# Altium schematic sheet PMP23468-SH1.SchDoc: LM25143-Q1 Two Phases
size 431 x 279 mm; Date: Not shown in title block; ApprovedBy: Not shown in title block; CheckedBy: Not shown in title block; Author: Not shown in title block; CompanyName: Not shown in title block; Engineer: Not shown in title block; Organization: Not shown in title block; Address1: Not shown in title block; Address2: Not shown in title block; Address3: Not shown in title block; Address4: Not shown in title block; DocumentNumber: 1; Revision: Use project parameter SCH_Rev; SheetNumber: 1; SheetTotal: 2; PageSetup: Record=PageOptions¦CenterHorizontal=True¦CenterVertical=True¦PrintScale=0.96¦XCorrection=1.00¦YCorrection=1.00¦PrintKind=0¦BorderSize=5000000¦LeftOffset=0¦BottomOffset=0¦Orientation=2¦PaperLength=1000¦PaperWidth=1000¦Scale=100¦PaperSource=7¦PrintQuality=600¦MediaType=1¦DitherType=10¦PaperKind=11" x 17"¦PrintScaleMode=1
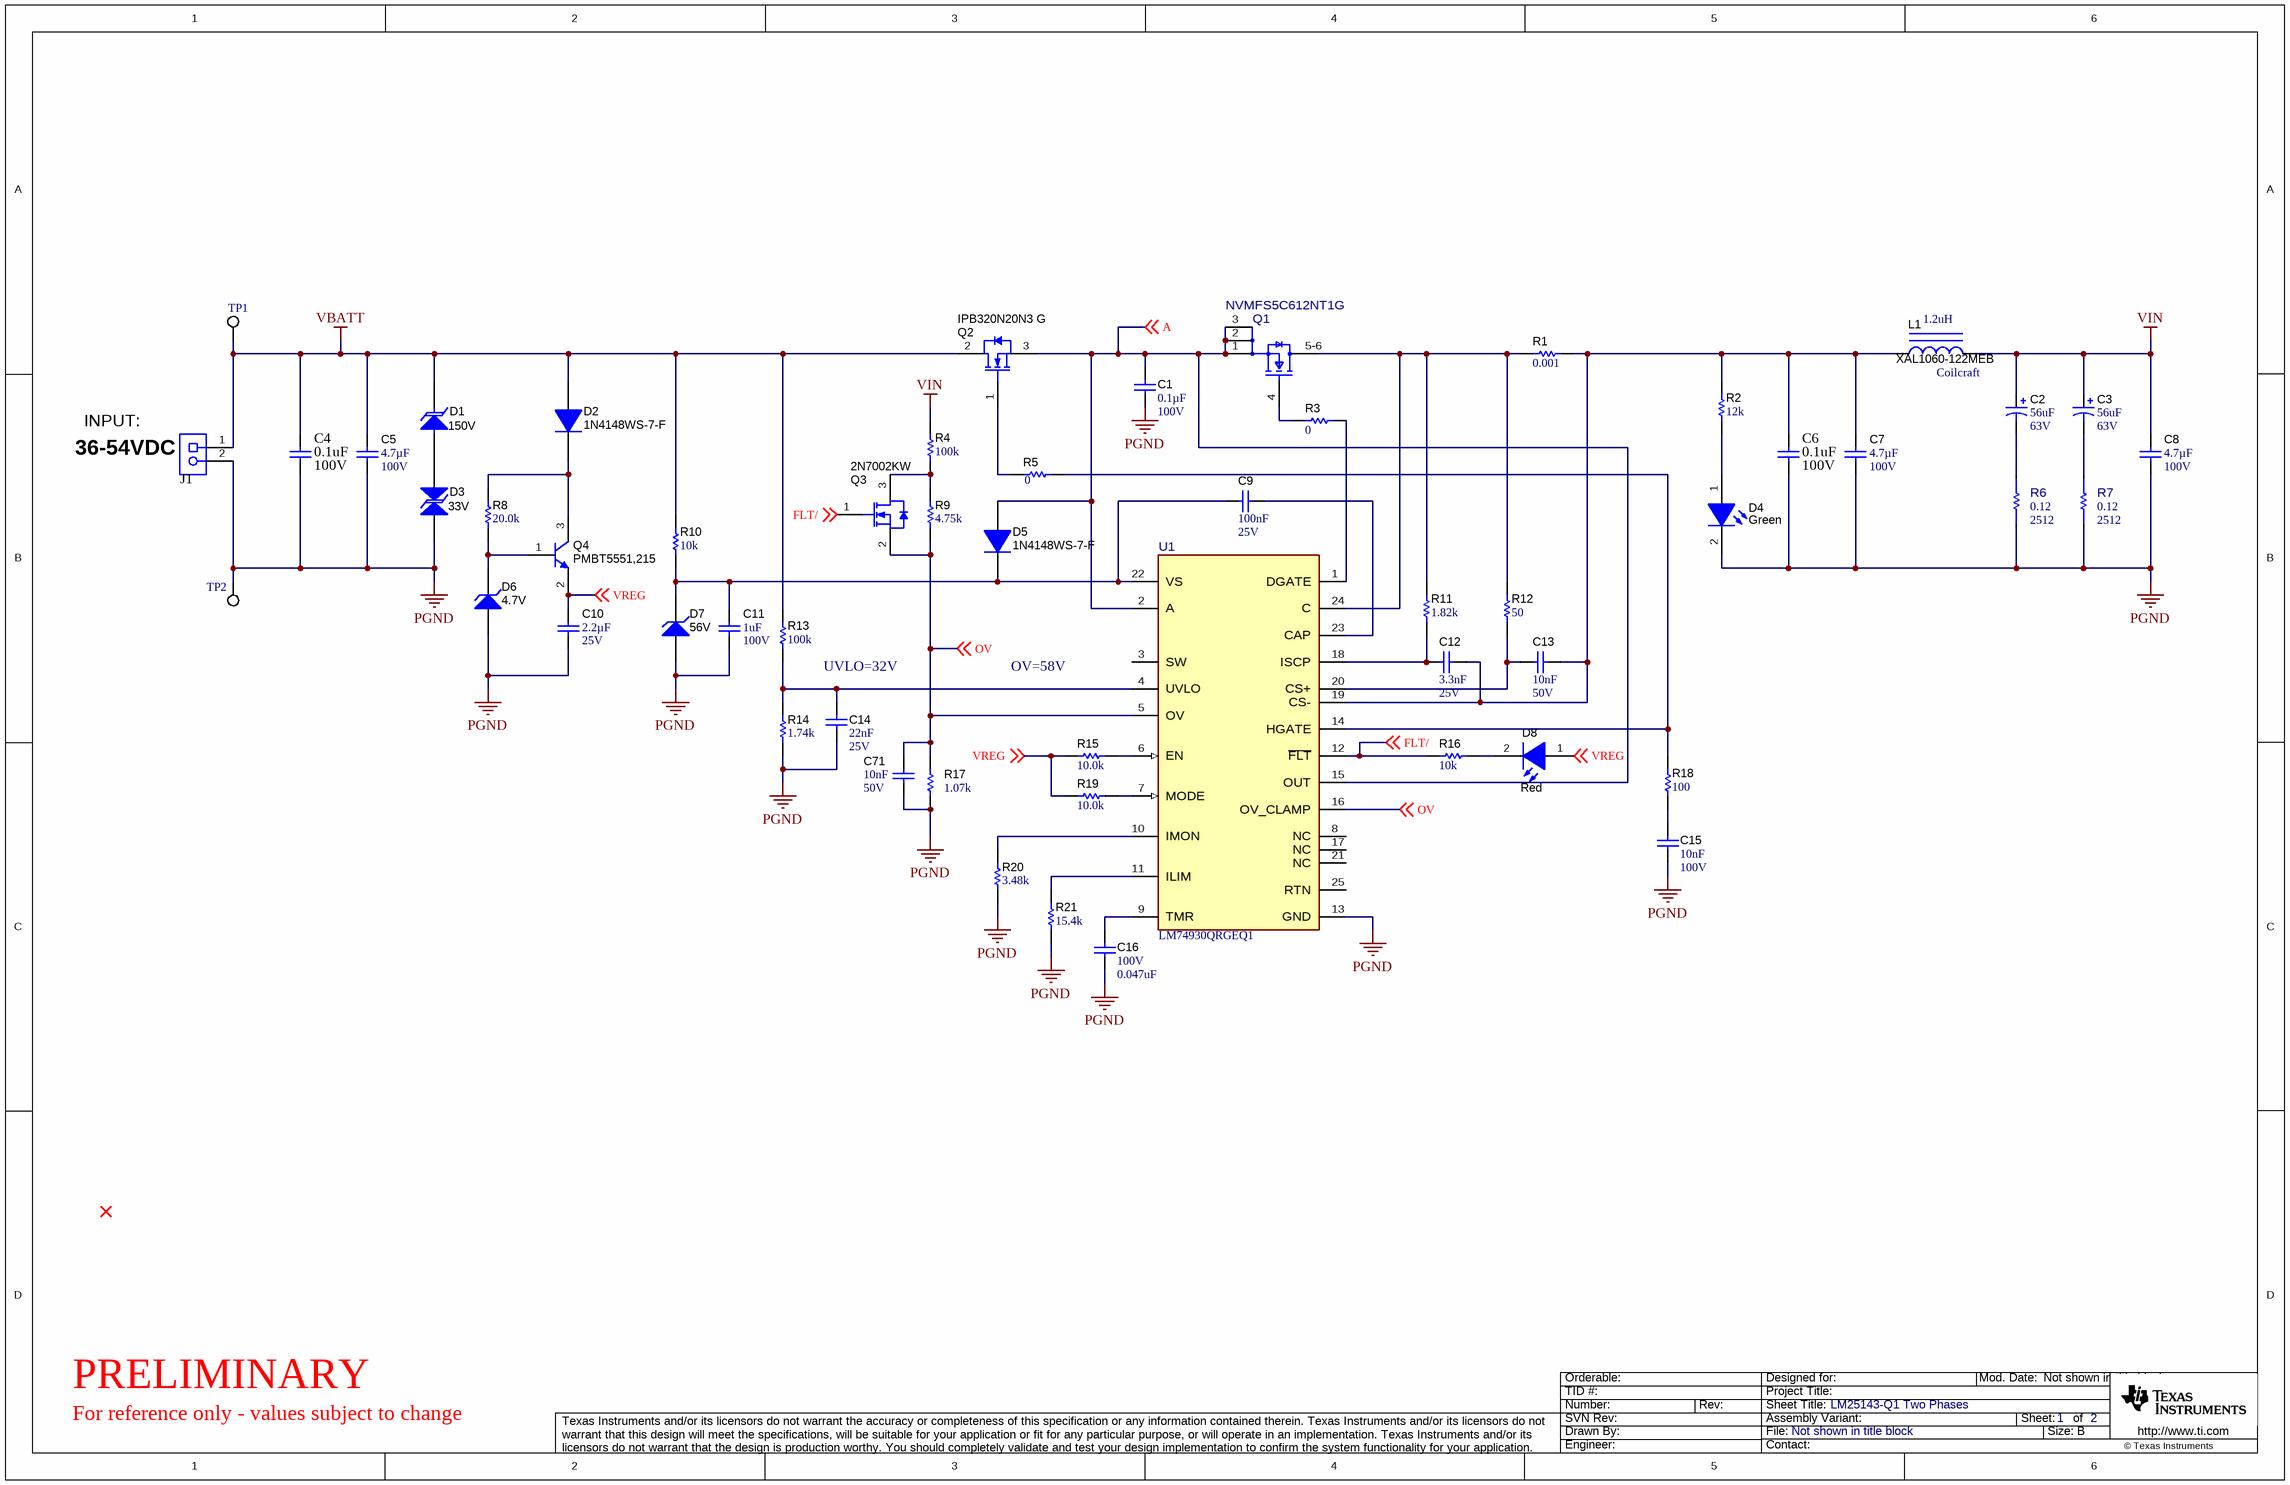
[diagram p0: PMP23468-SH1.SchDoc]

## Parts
C1  ValueDisplayed: 0.1µF  VDC_V: 100V  [0603]  (hidden comment: GCJ188L8EL104KA07D)
C2  VDC_V: 63V  ValueDisplayed: 56uF  [SM_RADIAL_10BMM]  (hidden comment: EEHZC1J560P)
C3  VDC_V: 63V  ValueDisplayed: 56uF  [SM_RADIAL_10BMM]  (hidden comment: EEHZC1J560P)
C4  Value2: 100V  ValueDisplayed: 0.1uF  [0805_HV]  (hidden comment: C0805C104K1RACTU)
C5  VDC_V: 100V  ValueDisplayed: 4.7µF  [1210_220]  (hidden comment: GCM32DC72A475KE02L)
C6  Value2: 100V  ValueDisplayed: 0.1uF  [0805_HV]  (hidden comment: C0805C104K1RACTU)
C7  VDC_V: 100V  ValueDisplayed: 4.7µF  [1210_220]  (hidden comment: GCM32DC72A475KE02L)
C8  VDC_V: 100V  ValueDisplayed: 4.7µF  [1210_220]  (hidden comment: GCM32DC72A475KE02L)
C9  Cap_F: 100nF  VDC_V: 25V  [0603]  (hidden comment: CGA3E2X7R1E104K080AA)
C10  Cap_F: 2.2µF  VDC_V: 25V  [0805_HV]  (hidden comment: GCM21BR71E225KA73L)
C11  VDC_V: 100V  ValueDisplayed: 1uF  [1206_180]  (hidden comment: GCM31CR72A105KA03)
C12  Cap_F: 3.3nF  VDC_V: 25V  [0603]  (hidden comment: GRM188R71E332KA01D)
C13  Cap_F: 10nF  VDC_V: 50V  [0603]  (hidden comment: GCM188R71H103KA37D)
C14  Cap_F: 22nF  VDC_V: 25V  [0603]  (hidden comment: C0603C223K3RACTU)
C15  Cap_F: 10nF  VDC_V: 100V  [0603]  (hidden comment: CGA3E2X7R2A103K080AA)
C16  VDC_V: 100V  ValueDisplayed: 0.047uF  [0603]  (hidden comment: CGA3E3X7S2A473K080AB)
C71  Cap_F: 10nF  VDC_V: 50V  [0603]  (hidden comment: GCM188R71H103KA37D)
D1  value 150V  [SMB]  (hidden comment: SMBJ150A-13-F)
D2  1N4148WS-7-F  [SOD-323]
D3  value 33V  [SMB-Bi]  (hidden comment: SMBJ33CA-13-F)
D4  value Green  [LED_LTST-C190]  (hidden comment: LTST-C190GKT)
D5  1N4148WS-7-F  [SOD-323]
D6  value 4.7V  [SOD-323]  (hidden comment: MM3Z4V7ST1G)
D7  value 56V  [SOD-123]  (hidden comment: MMSZ5263BT1G)
D8  value Red  [LED_LTST-C170_Red]  (hidden comment: LTST-C170KRKT)
J1  1714971  [Phoenix_1714971]  (value not drawn)
L1  XAL1060-122MEB  Manufacturer: Coilcraft  ValueDisplayed: 1.2uH  [XAL1060]
Q1  NVMFS5C612NT1G  [FP-NVMFS5C612NT1G_DFN5-MFG]
Q2  IPB320N20N3 G  [DDPAK]
Q3  2N7002KW  [SOT-323]
Q4  PMBT5551,215  [SOT-23]
R1  ValueDisplayed: 0.001  [2010]  (hidden comment: WSL20101L000FEA)
R2  ValueDisplayed: 12k  [0603]  (hidden comment: CRCW060312K0JNEA)
R3  ValueDisplayed: 0  [0603]  (hidden comment: ERJ-3GEY0R00V)
R4  ValueDisplayed: 100k  [0603]  (hidden comment: CRCW0603100KFKEA)
R5  ValueDisplayed: 0  [0603]  (hidden comment: ERJ-3GEY0R00V)
R6  PackageReference: 2512  Res_ohm: 0.12  [FP-TLRH3AWTTER120F_2512-MFG]  (hidden comment: TLRH3AWTTER120F)
R7  PackageReference: 2512  Res_ohm: 0.12  [FP-TLRH3AWTTER120F_2512-MFG]  (hidden comment: TLRH3AWTTER120F)
R8  ValueDisplayed: 20.0k  [0805_HV]  (hidden comment: ERJ-6ENF2002V)
R9  ValueDisplayed: 4.75k  [0603]  (hidden comment: CRCW06034K75FKEA)
R10  ValueDisplayed: 10k  [1206]  (hidden comment: CRCW120610K0JNEA)
R11  ValueDisplayed: 1.82k  [0603]  (hidden comment: CRCW0603464RFKEA)
R12  ValueDisplayed: 50  [0603]  (hidden comment: CRCW060350R0FKEA)
R13  ValueDisplayed: 100k  [0603]  (hidden comment: CRCW0603100KFKEA)
R14  ValueDisplayed: 1.74k  [0603]  (hidden comment: CRCW06031K74FKEA)
R15  ValueDisplayed: 10.0k  [0603]  (hidden comment: RMCF0603FT10K0)
R16  ValueDisplayed: 10k  [1206]  (hidden comment: CRCW120610K0JNEA)
R17  ValueDisplayed: 1.07k  [0603]  (hidden comment: CRCW06031K10FKEA)
R18  ValueDisplayed: 100  [0603]  (hidden comment: CRCW0603100RJNEA)
R19  ValueDisplayed: 10.0k  [0603]  (hidden comment: RMCF0603FT10K0)
R20  ValueDisplayed: 3.48k  [0603]  (hidden comment: RC0603FR-0736KL)
R21  ValueDisplayed: 15.4k  [0603]  (hidden comment: CRCW060324K3FKEA)
TP1  5015  [Testpoint_Keystone_Miniature]  (value not drawn)
TP2  5015  [Testpoint_Keystone_Miniature]  (value not drawn)
U1  LM74930QRGEQ1  [RGE0024T-MFG]

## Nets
PGND: C1.2 C4.1 C5.2 C6.2 C7.2 C8.2 C10.2 C11.2 C14.2 C15.2 C16.2 C71.1 D3.2 D4.2(K) D6.2(A) D7.2(A) J1.2 R6.1 R7.1 R14.2 R17.2 R20.1 R21.2 TP2.1 U1.13(GND)
VBATT: C4.2 C5.1 D1.1(K) D2.2(A) J1.1 Q2.2(D) R10.1 R13.1 TP1.1
VIN: C2.1(+) C3.1(+) C8.1 L1.2 R4.1
A: C1.1 D5.2(A) Q1.1(S) Q1.2(S) Q1.3(S) Q2.3(S) U1.2(A) U1.15(OUT) ; off-sheet A
FLT/: Q3.1(G) R16.1 U1.12(~{FLT}) ; off-sheet FLT/
OV: C71.2 Q3.2(S) R9.2 R17.1 U1.5(OV) U1.16(OV_CLAMP) ; off-sheet OV
VREG: C10.1 D8.1(A) Q4.2(E) R15.1 R19.1 ; off-sheet VREG
NetC2_2: C2.2(-) R6.2
NetC3_2: C3.2(-) R7.2
NetC6_1: C6.1 C7.1 C12.2 C13.2 L1.1 R1.2 R2.1 U1.19(CS-)
NetC9_1: C9.1 C11.1 D5.1(K) D7.1(K) R10.2 U1.22(VS)
NetC9_2: C9.2 U1.23(CAP)
NetC12_1: C12.1 R11.2 U1.18(ISCP)
NetC13_1: C13.1 R12.2 U1.20(CS+)
NetC14_1: C14.1 R13.2 R14.1 U1.4(UVLO)
NetC15_1: C15.1 R18.2
NetC16_1: C16.1 U1.9(TMR)
NetD1_2: D1.2(A) D3.1
NetD2_1: D2.1(K) Q4.3(C) R8.1
NetD4_1: D4.1(A) R2.2
NetD6_1: D6.1(K) Q4.1(B) R8.2
NetD8_2: D8.2(K) R16.2
NetQ1_4: Q1.4(G) R3.1
NetQ1_5-6: Q1.5-6(D) R1.1 R11.1 R12.1 U1.24(C)
NetQ2_1: Q2.1(G) R5.1
NetQ3_3: Q3.3(D) R4.2 R9.1
NetR3_2: R3.2 U1.1(DGATE)
NetR5_2: R5.2 R18.1 U1.14(HGATE)
NetR15_2: R15.2 U1.6(EN)
NetR19_2: R19.2 U1.7(MODE)
NetR20_2: R20.2 U1.10(IMON)
NetR21_1: R21.1 U1.11(ILIM)

Not connected (* = marked no-connect by the designer): U1 3(SW) 8(NC) 17(NC) 21(NC) 25(RTN)

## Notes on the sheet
- INPUT:
- (near J1) 36-54VDC
- UVLO=32V
- OV=58V
- PRELIMINARY
- For reference only - values subject to change

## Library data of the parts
C1 = CMP-0860999-1: CAP, CERM, 0.1 µF, 100 V,+/- 10%, X8L, AEC-Q200 Grade 0, 0603; Manufacturer: MuRata; Cap_F: 100nF; TaMax_C: 150°C; SizeAreaWB_mm2: 4.68; SizeArea_mm2: 1.28; Value: 0.1uF; SizeZ_mm: 1; AEC Qualified: Y; SizeX_mm: 1.6; AEC Grade: 0; SizeY_mm: 0.8; U/M: EA; TaMin_C: -55°C; Polarized: N; AEC Category: Q200
C2 C3 = CMP-0012603-3: CAP, Polymer Hybrid, 56 uF, 63 V, +/- 20%, 30 ohm, 10x10 SMD; Manufacturer: Panasonic; TaMin_C: -55°C; ESR_ohm: 30; Polarized: Y; SizeAreaWB_mm2: 159.9; Value1: 30 ohm; Value: 56uF; TaMax_C: 125°C; SizeZ_mm: 10.2; SizeX_mm: 11; SizeY_mm: 10.3; SizeArea_mm2: 113.3; CompType: Capacitor; Cap_F: 56µF; IRMS_A: 1.4A; AEC Category: Q200
C4 C6 = CMP-0007722-2: CAP, CERM, 0.1 uF, 100 V, +/- 10%, X7R, 0805; Manufacturer: Kemet; TaMin_C: -55°C; ESR_ohm: 0.064; Polarized: N; SizeAreaWB_mm2: 6.75; Value1: 0.064 ohm; U/M: EA; Value: 0.1uF; TaMax_C: 125°C; SizeZ_mm: 1.45; SizeX_mm: 2; SizeY_mm: 1.25; Cap_Case: 0805; SizeArea_mm2: 2.5; CompType: Capacitor; Cap_F: 100nF; IRMS_A: 1.64A; AEC Category: Q200
C5 C7 C8 = CMP-0082268-1: CAP, CERM, 4.7 µF, 100 V,+/- 10%, X7S, AEC-Q200 Grade 1, 1210; Manufacturer: MuRata; TaMin_C: -55°C; ESR_ohm: 1m; Polarized: N; SizeAreaWB_mm2: 14.7; Value1: 0.001 ohm; U/M: EA; Value: 4.7uF; TaMax_C: 125°C; SizeZ_mm: 2.2; SizeX_mm: 3.2; SizeY_mm: 2.5; Cap_Case: 1210; SizeArea_mm2: 8; AEC Qualified: Y; IRMS_A: 6A; AEC Grade: 1; AEC Category: Q200
C9 = CMP-0007077-5: CAP, CERM, 0.1 uF, 25 V, +/- 10%, X7R, AEC-Q200 Grade 1, 0603; Manufacturer: TDK; TaMin_C: -55°C; Polarized: N; SizeAreaWB_mm2: 4.68; Value1: Unknown; U/M: EA; Value: 0.1uF; TaMax_C: 125°C; SizeZ_mm: 1; SizeX_mm: 1.6; SizeY_mm: 0.8; SizeArea_mm2: 1.28; AEC Qualified: Y; AEC Category: Q200
C10 = CMP-0083622-1: CAP, CERM, 2.2 µF, 25 V,+/- 10%, X7R, AEC-Q200 Grade 1, 0805; Manufacturer: MuRata; TaMin_C: -55°C; Polarized: N; SizeAreaWB_mm2: 6.75; U/M: EA; Value: 2.2uF; TaMax_C: 125°C; SizeZ_mm: 1.45; SizeX_mm: 2; SizeY_mm: 1.25; Cap_Case: 0805; SizeArea_mm2: 2.5; AEC Qualified: Y; AEC Grade: 1; AEC Category: Q200
C11 = CMP-0008815-2: CAP, CERM, 1 uF, 100 V, +/- 10%, X7R, AEC-Q200 Grade 1, 1206; Manufacturer: MuRata; TaMin_C: -55°C; Polarized: N; SizeAreaWB_mm2: 10.92; Value1: Unknown; U/M: EA; Value: 1uF; TaMax_C: 125°C; SizeZ_mm: 1.8; SizeX_mm: 3.2; SizeY_mm: 1.6; Cap_Case: 1206; SizeArea_mm2: 5.12; AEC Qualified: Y; Cap_F: 1µF; AEC Grade: 1; AEC Category: Q200
C12 = CMP-0007418-4: CAP, CERM, 3300 pF, 25 V, +/- 10%, X7R, 0603; Manufacturer: MuRata; TaMin_C: -55°C; Polarized: N; SizeAreaWB_mm2: 4.68; Value1: Unknown; U/M: EA; Value: 3300pF; TaMax_C: 125°C; SizeZ_mm: 1; SizeX_mm: 1.6; SizeY_mm: 0.8; SizeArea_mm2: 1.28; AEC Category: Q200
C13 = CMP-0007143-4: CAP, CERM, 0.01 uF, 50 V, +/- 10%, X7R, AEC-Q200 Grade 1, 0603; Manufacturer: MuRata; TaMin_C: -55°C; Polarized: N; SizeAreaWB_mm2: 4.68; Value1: Unknown; U/M: EA; Value: 0.01uF; TaMax_C: 125°C; SizeZ_mm: 1; SizeX_mm: 1.6; SizeY_mm: 0.8; SizeArea_mm2: 1.28; AEC Qualified: Y; AEC Category: Q200
C14 = CMP-0006899-4: CAP, CERM, 0.022 uF, 25 V, +/- 10%, X7R, 0603; Manufacturer: Kemet; TaMin_C: -55°C; Polarized: N; SizeAreaWB_mm2: 4.68; Value1: Unknown; U/M: EA; TaMax_C: 125°C; SizeZ_mm: 1; SizeX_mm: 1.6; SizeY_mm: 0.8; SizeArea_mm2: 1.28; AEC Category: Q200
C15 = CMP-0007082-4: CAP, CERM, 0.01 uF, 100 V, +/- 10%, X7R, AEC-Q200 Grade 1, 0603; Manufacturer: TDK; TaMin_C: -55°C; ESR_ohm: 0.2354; Polarized: N; SizeAreaWB_mm2: 4.68; Value1: 0.235428 ohm; U/M: EA; Value: 0.01uF; TaMax_C: 125°C; SizeZ_mm: 1; SizeX_mm: 1.6; SizeY_mm: 0.8; SizeArea_mm2: 1.28; AEC Qualified: Y; IRMS_A: 396.995mA; AEC Category: Q200
C16 = CMP-0007101-4: CAP, CERM, 0.047 uF, 100 V, +/- 10%, X7S, AEC-Q200 Grade 1, 0603; Manufacturer: TDK; TaMin_C: -55°C; ESR_ohm: 89.796m; Polarized: N; SizeAreaWB_mm2: 4.68; Value1: 0.089796 ohm; U/M: EA; TaMax_C: 125°C; SizeZ_mm: 1; SizeX_mm: 1.6; SizeY_mm: 0.8; SizeArea_mm2: 1.28; AEC Qualified: Y; Cap_F: 47nF; IRMS_A: 567.484mA; AEC Category: Q200
C71 = CMP-0007143-4: CAP, CERM, 0.01 uF, 50 V, +/- 10%, X7R, AEC-Q200 Grade 1, 0603 (stack on top of R17 resistor); Manufacturer: MuRata; TaMin_C: -55°C; Polarized: N; SizeAreaWB_mm2: 4.68; Value1: Unknown; U/M: EA; Value: 0.01uF; TaMax_C: 125°C; SizeZ_mm: 1; SizeX_mm: 1.6; SizeY_mm: 0.8; SizeArea_mm2: 1.28; AEC Qualified: Y; AEC Category: Q200
D1 = CMP-0005577-3: Diode, TVS, Uni, 150 V, 243 Vc, SMB; Manufacturer: Diodes Inc.; Vbr_Max: 192.5V; Ipp: 2.5A; AEC Category: Q101; SizeArea_mm2: 21.336; Value1: 600W; SizeAreaWB_mm2: 44.156; Vc: 243V; SizeZ_mm: 2.6; SizeX_mm: 5.6; SizeY_mm: 3.81; Vbr_Min: 167V
D2 D5 = CMP-0079597-2: Diode, Switching, 75 V, 0.15 A, AEC-Q101, SOD-323; Manufacturer: Diodes Inc.; SizeX_mm: 2.7; Vf_V: 1.25V; AEC Qualified: Y; SizeArea_mm2: 3.645; AEC Category: Q101; SizeAreaWB_mm2: 8.695; Io_A: 150mA; SizeZ_mm: 1; Value1: 0.15A; SizeY_mm: 1.35; TJmax_C: 150°C; Vr_V: 75V; Value: 75V
D3 = CMP-0005564-3: Diode, TVS, Bi, 33 V, SMB; Manufacturer: Diodes Inc.; SizeX_mm: 5.6; Ppk: 600W; SizeAreaWB_mm2: 44.156; SizeZ_mm: 2.6; SizeArea_mm2: 21.336; SizeY_mm: 3.81; AEC Category: Q101
D4 = CMP-0002827-3: LED, Green, SMD; Manufacturer: Lite-On; Power_TotalModule: 100mW; Value2: 2.1V; Io_A: 20mA; Value1: 0.1W
D6 = CMP-0085737-1: Diode, Zener, 4.7 V, 300 mW, SOD-323; Manufacturer: ON Semiconductor; SizeArea_mm2: 3.645; SizeZ_mm: 1; SizeAreaWB_mm2: 8.695; RJA_CperW: 416; SizeY_mm: 1.35; Power_W: 300mW; AEC Qualified: N; SizeX_mm: 2.7; AEC Category: Q101; Value1: 0.3W
D7 = CMP-0005738-4: Diode, Zener, 56 V, 500 mW, AEC-Q101, SOD-123; Manufacturer: ON Semiconductor; AEC Qualified: Y; Value1: 0.5W; SizeY_mm: 1.7; SizeX_mm: 3.85; SizeArea_mm2: 6.545; AEC Category: Q101; SizeAreaWB_mm2: 13.095; Power_W: 500mW; SizeZ_mm: 1.35; RJA_CperW: 340
D8 = CMP-0002829-3: LED, Red, SMD; Manufacturer: Lite-On; SizeZ_mm: 1.2; Value1: W; SizeY_mm: 1.25; Value2: 2V; SizeArea_mm2: 2.5; SizeX_mm: 2; SizeAreaWB_mm2: 6.75; Io_A: 20mA; Type: AlInGaP
J1 = CMP-0055554-1: Receptacle, 9.52mm, 2x1, TH; Manufacturer: Phoenix Contact; CNHeader: FALSE; Current_A: 32A; Gender: Female; Cert_CSA: Y; Voltage_V: 1kV; Row_Count: 1; Pitch_mm: 9.52
L1 = CMP-0060959-1: Inductor, Shielded, Composite, 1.2 uH, 26.3 A, 0.0025 ohm, AEC-Q200 Grade 1, SMD; Isat: 43A @ 30% inductance drop; Irms: 26.3A @ 40C rise; Green_Lifecycle: Not Set; SizeAreaWB_mm2: 159.6; DCR_ohm: 2.5m; Green_REACh: Incomplete; Value: 1.2uH; Imax_A: 26.3A; SizeZ_mm: 6; SizeX_mm: 11.3; SizeY_mm: 10; SizeArea_mm2: 113; Ind_H: 1.2µH; AEC Qualified: Y; AEC Grade: 1; AEC Category: Q200
Q1 = CMP-0093804-1: Single N-Channel Power MOSFET 60V, 225A, 1.65ohm; Manufacturer: onsemi; Turn On Delay Time: 13.2ns; Standoff Height: 0mm; TJmax_C: +175°C; Rdson45_ohm: 1.35m; Turn Off Delay Time: 46.5ns; Number Of N Channels: 1; Vgs_V: 20V; Reverse Recovery Charge: 160nC; AEC Grade: Grade 0; Threshold Vgs Min: 2V; Rthja Max: 39°C/W; QgTyp_nC: 62nC @ 10V; Reverse Recovery Time: 90ns; VdsMax_V: 1.2V; Input Capacitace At Vds: 4900pF @ 25V; Power_W: 3.8W; AEC Qualified: Yes; SizeZ_mm: 1.1mm; Pulse Drain Current: 900A; ChMode: False; Threshold Vgs Max: 4V; Typ Forward Diode Voltage: 0.81V
Q2 = CMP-0001084-3: MOSFET, N-CH, 200 V, 34 A, DDPAK; Manufacturer: Infineon Technologies; Alternate Manufacturer: None; Value2: 22 nC; QgTyp_nC: 22; SizeZ_mm: 4.445; Value: 200V; SizeAreaWB_mm2: 209.6992; Rdson45_ohm: 0.25; Value1: 0.2; SizeArea_mm2: 154.8892; AEC Category: Q101; ChMode: Enhancement; SizeY_mm: 10.16; SizeX_mm: 15.245; ChType: N; Vgs_V: 20V; IdsMax_A: 34A
Q3 = CMP-0000774-1: MOSFET, N-CH, 60 V, 0.31 A, SOT-323; Manufacturer: Fairchild Semiconductor; Alternate Manufacturer: None; SizeZ_mm: 1.1; Value: 60V; SizeAreaWB_mm2: 10.24; Rdson45_ohm: 1.6; Value1: 1; SizeArea_mm2: 4.84; AEC Category: Q101; SizeY_mm: 2.2; ChType: N; Vgs_V: 2.1V; IdsMax_A: 310mA; U/M: EA
Q4 = CMP-0750056-1: Transistor, NPN, 160 V, 0.3 A, SOT-23; Manufacturer: Nexperia; TaMax_C: 150°C; IcRated_A: 300mA; SizeX_mm: 2.5; NPN: 1; AEC Qualified: N; TaMin_C: -65°C; PNP: 0; SizeArea_mm2: 7.5; SizeY_mm: 3; SizeAreaWB_mm2: 14; CompType: BJT; SizeZ_mm: 1.1; Vcesat1_V: 150mV; Value: 160 V; Value2: 250; Vceo_V: 160V; AEC Category: Q101; Value1: 0.3 A
R1 = CMP-0016548-2: RES, 0.001, 1%, 0.5 W, 2010; Manufacturer: Vishay-Dale; Power_W: 500mW; TempCo: 275 ppm/C; Value_Code: 1L000; U/M: EA; Value: 0.001; EIA_Code: E96; Res_ohm: 1m; SizeX_mm: 5; SizeY_mm: 2.5; SizeZ_mm: 1.66; Value2: 0.5W; SizeArea_mm2: 12.5; AEC Category: Q200
R2 = CMP-0025711-4: RES, 12 k, 5%, 0.1 W, AEC-Q200 Grade 0, 0603; Manufacturer: Vishay-Dale; Power_W: 100mW; TempCo: 200 ppm/C; Value_Code: 12k0; Value: 12k; EIA_Code: E24; SizeX_mm: 1.6; SizeY_mm: 0.8; SizeZ_mm: 1; Value2: 0.1W; SizeArea_mm2: 1.28; AEC Qualified: Y; VDC_V: 75V; AEC Category: Q200; AEC Grade: 0
R3 R5 = CMP-0025874-4: RES, 0, 5%, 0.1 W, AEC-Q200 Grade 0, 0603; Manufacturer: Panasonic; Power_W: 100mW; TempCo: 600 ppm/C; Value_Code: 0000; Value: 0; EIA_Code: E24; SizeX_mm: 1.6; SizeY_mm: 0.8; SizeZ_mm: 1; Value2: 0.1W; SizeArea_mm2: 1.28; AEC Qualified: Y; VDC_V: 50V; AEC Category: Q200; SizeAreaWB_mm2: 4.68
R4 R13 = CMP-0021990-4: RES, 100 k, 1%, 0.1 W, AEC-Q200 Grade 0, 0603; Manufacturer: Vishay-Dale; Power_W: 100mW; TempCo: 100 ppm/C; Value: 100k; EIA_Code: E96; SizeX_mm: 1.6; SizeY_mm: 0.8; SizeZ_mm: 1; Value2: 0.1W; SizeArea_mm2: 1.28; AEC Qualified: Y; VDC_V: 75V; AEC Category: Q200; AEC Grade: 0
R6 R7 = CMP-0088454-1: 120 mOhms ±1% 2W Chip Resistor 2512 (6432 Metric) Automotive AEC-Q200, Current Sense Metal Element; Manufacturer: KOA Speer; TempCo: 50ppm/°C; SizeZ_mm: 0.7mm; AEC Qualified: Yes; AEC Grade: Grade 0
R8 = CMP-0021614-3: RES, 20.0 k, 1%, 0.125 W, AEC-Q200 Grade 0, 0805; Manufacturer: Panasonic; Power_W: 125mW; TempCo: 100 ppm/C; Value_Code: 20k0; Value: 20.0k; EIA_Code: E96; Res_ohm: 20k; SizeX_mm: 2; SizeY_mm: 1.25; SizeZ_mm: 1.45; Value2: 0.125W; SizeArea_mm2: 2.5; AEC Qualified: Y; AEC Category: Q200; AEC Grade: 0; SizeAreaWB_mm2: 6.75
R9 = CMP-0022456-4: RES, 4.75 k, 1%, 0.1 W, AEC-Q200 Grade 0, 0603; Manufacturer: Vishay-Dale; Power_W: 100mW; TempCo: 100 ppm/C; Value_Code: 4k75; Value: 4.75k; EIA_Code: E96; SizeX_mm: 1.6; SizeY_mm: 0.8; SizeZ_mm: 1; Value2: 0.1W; SizeArea_mm2: 1.28; AEC Qualified: Y; VDC_V: 75V; AEC Category: Q200; AEC Grade: 0
R10 R16 = CMP-0018576-3: RES, 10 k, 5%, 0.25 W, AEC-Q200 Grade 0, 1206; Manufacturer: Vishay-Dale; Power_W: 250mW; TempCo: 200 ppm/C; Value_Code: 10k0; Value: 10k; EIA_Code: E24; SizeX_mm: 3.2; SizeY_mm: 1.6; SizeZ_mm: 1.35; Value2: 0.25W; SizeArea_mm2: 5.12; AEC Qualified: Y; VDC_V: 200V; AEC Category: Q200; AEC Grade: 0
R11 = CMP-0022134-4: RES, 1.82 k, 1%, 0.1 W, AEC-Q200 Grade 0, 0603; Manufacturer: Vishay-Dale; PartNumber: CRCW06031K82FKEA; Power_W: 100mW; TempCo: 100 ppm/C; Value_Code: 1k82; Value: 1.82k; EIA_Code: E96; SizeX_mm: 1.6; SizeY_mm: 0.8; SizeZ_mm: 1; Value2: 0.1W; SizeArea_mm2: 1.28; AEC Qualified: Y; VDC_V: 75V; AEC Category: Q200; AEC Grade: 0
R12 = CMP-0022479-4: RES, 50, 1%, 0.1 W, AEC-Q200 Grade 0, 0603; Manufacturer: Vishay-Dale; Power_W: 100mW; TempCo: 100 ppm/C; Value_Code: 50R0; Value: 50; SizeX_mm: 1.6; SizeY_mm: 0.8; SizeZ_mm: 1; Value2: 0.1W; SizeArea_mm2: 1.28; AEC Qualified: Y; VDC_V: 75V; AEC Category: Q200; AEC Grade: 0
R14 = CMP-0022132-4: RES, 1.74 k, 1%, 0.1 W, AEC-Q200 Grade 0, 0603; Manufacturer: Vishay-Dale; Power_W: 100mW; TempCo: 100 ppm/C; Value_Code: 1k74; Value: 1.74k; EIA_Code: E96; SizeX_mm: 1.6; SizeY_mm: 0.8; SizeZ_mm: 1; Value2: 0.1W; SizeArea_mm2: 1.28; AEC Qualified: Y; VDC_V: 75V; AEC Category: Q200; AEC Grade: 0
R15 R19 = CMP-0023341-3: RES, 10.0 k, 1%, 0.1 W, AEC-Q200 Grade 0, 0603; Manufacturer: Stackpole Electronics Inc; Power_W: 100mW; TempCo: 100 ppm/C; Value_Code: 10k0; U/M: EA; Value: 10.0k; EIA_Code: E96; Res_ohm: 10k; SizeX_mm: 1.6; SizeY_mm: 0.8; SizeZ_mm: 1; Value2: 0.1W; SizeArea_mm2: 1.28; AEC Qualified: Y; VDC_V: 75V; AEC Grade: 0; AEC Category: Q200
R17 = CMP-0022112-4: RES, 1.07 k, 1%, 0.1 W, AEC-Q200 Grade 0, 0603; Manufacturer: Vishay-Dale; PartNumber: CRCW06031K07FKEA; Power_W: 100mW; TempCo: 100 ppm/C; Value_Code: 1k07; Value: 1.07k; EIA_Code: E96; SizeX_mm: 1.6; SizeY_mm: 0.8; SizeZ_mm: 1; Value2: 0.1W; SizeArea_mm2: 1.28; AEC Qualified: Y; VDC_V: 75V; AEC Category: Q200; AEC Grade: 0
R18 = CMP-0025700-4: RES, 100, 5%, 0.1 W, AEC-Q200 Grade 0, 0603; Manufacturer: Vishay-Dale; Power_W: 100mW; TempCo: 200 ppm/C; Value_Code: 100R; Value: 100; EIA_Code: E24; SizeX_mm: 1.6; SizeY_mm: 0.8; SizeZ_mm: 1; Value2: 0.1W; SizeArea_mm2: 1.28; AEC Qualified: Y; VDC_V: 75V; AEC Category: Q200; AEC Grade: 0
R20 = CMP-0022377-4: RES, 3.48 k, 1%, 0.1 W, AEC-Q200 Grade 0, 0603; Manufacturer: Vishay-Dale; PartNumber: CRCW06033K48FKEA; Power_W: 100mW; TempCo: 100 ppm/C; Value_Code: 3k48; Value: 3.48k; EIA_Code: E96; SizeX_mm: 1.6; SizeY_mm: 0.8; SizeZ_mm: 1; Value2: 0.1W; SizeArea_mm2: 1.28; AEC Qualified: Y; VDC_V: 75V; AEC Category: Q200; AEC Grade: 0
R21 = CMP-0022067-4: RES, 15.4 k, 1%, 0.1 W, AEC-Q200 Grade 0, 0603; Manufacturer: Vishay-Dale; PartNumber: CRCW060315K4FKEA; Power_W: 100mW; TempCo: 100 ppm/C; Value_Code: 15k4; Value: 15.4k; EIA_Code: E96; SizeX_mm: 1.6; SizeY_mm: 0.8; SizeZ_mm: 1; Value2: 0.1W; SizeArea_mm2: 1.28; AEC Qualified: Y; VDC_V: 75V; AEC Category: Q200; AEC Grade: 0
TP1 TP2 = CMP-0055152-2: Test Point, Miniature, SMT; Manufacturer: Keystone Electronics; CNHeader: FALSE; Green_Lifecycle: Active; Green_REACh: Passed; CT: TRUE
U1 = CMP-0021701-1: Ideal Diode Surge Stopper with Circuit breaker, overvoltage protection and fault output; Manufacturer: Texas Instruments; SizeZ_mm: 1mm; AEC Qualified: Yes; AEC Grade: Grade 1; Max Supply Voltage: 65V; Min Supply Voltage: 3V; Nominal Supply Current: 650-700uA; Number Of Outputs: 1; Standoff Height: 0mm; TaMax_C: +125°C; TaMin_C: -40°C; TJmax_C: +150°C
